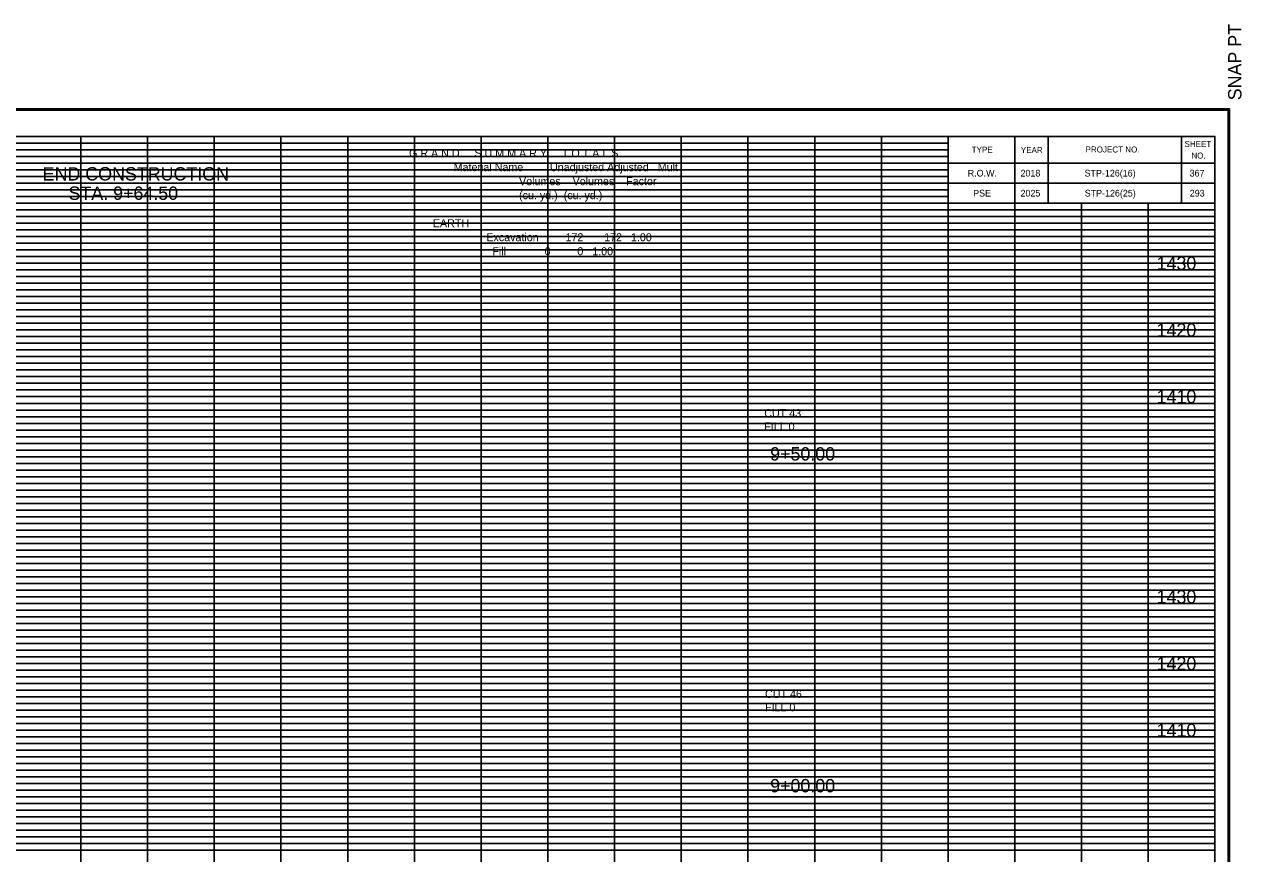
# Model space of a CAD drawing. Extents: x 980 to 1324, y 978 to 1227.
# Drawn here: x 1141.5 to 1324, y 1102.5 to 1226.8 of the extents above; entities that cross this region are included whole.
import ezdxf

# ---------------------------------------------------------------- set-up
doc = ezdxf.new("R2010")
doc.units = 0
for name, color, linetype in [('DESIGN - SCRATCH - User 1', 7, 'Continuous'), ('DESIGN - SHEET - Corner Text', 7, 'Continuous'), ('DESIGN - SHEET - Light Grid', 7, 'Continuous'), ('DESIGN - SHEET - Linework', 7, 'Continuous'), ('DESIGN - SHEET - Plot Shape', 7, 'Continuous'), ('DESIGN - TYPICAL - Text', 7, 'Continuous')]:
    doc.layers.add(name, color=color, linetype=linetype)

msp = doc.modelspace()

# ---------------------------------------------------------------- linework, layer by layer
at = {"layer": 'DESIGN - SCRATCH - User 1'}
for p, q in [((1285, 1204.5), (1285, 1204.5)), ((1292.4, 1204.5), (1292.4, 1204.5)), ((1304.9, 1204.5), (1304.9, 1204.5)), ((1317.4, 1204.5), (1317.4, 1204.5)), ((1285, 1201.5), (1285, 1201.5)), ((1292.4, 1201.5), (1292.4, 1201.5)), ((1304.9, 1201.5), (1304.9, 1201.5)), ((1317.4, 1201.5), (1317.4, 1201.5))]:
    msp.add_line(p, q, dxfattribs=at)
at = {"layer": 'DESIGN - SHEET - Light Grid'}
for p, q in [((1080, 1209), (1160, 1209)), ((1080, 1208), (1160, 1208)), ((1160, 1209), (1240, 1209)), ((1160, 1208), (1240, 1208)), ((1240, 1209), (1280, 1209)), ((1240, 1208), (1280, 1208)), ((1080, 1207), (1160, 1207)), ((1160, 1207), (1240, 1207)), ((1240, 1207), (1280, 1207)), ((1080, 1206), (1160, 1206)), ((1080, 1205), (1160, 1205)), ((1160, 1206), (1240, 1206)), ((1160, 1205), (1240, 1205)), ((1240, 1206), (1280, 1206)), ((1240, 1205), (1280, 1205)), ((1080, 1204), (1160, 1204)), ((1080, 1203), (1160, 1203)), ((1160, 1204), (1240, 1204)), ((1160, 1203), (1240, 1203)), ((1240, 1204), (1280, 1204)), ((1240, 1203), (1280, 1203)), ((1080, 1202), (1160, 1202)), ((1080, 1201), (1160, 1201)), ((1160, 1202), (1240, 1202)), ((1160, 1201), (1240, 1201)), ((1240, 1202), (1280, 1202)), ((1240, 1201), (1280, 1201)), ((1080, 1199), (1160, 1199)), ((1160, 1199), (1240, 1199)), ((1240, 1199), (1320, 1199)), ((1080, 1198), (1160, 1198)), ((1080, 1197), (1160, 1197)), ((1160, 1198), (1240, 1198)), ((1160, 1197), (1240, 1197)), ((1240, 1198), (1320, 1198)), ((1240, 1197), (1320, 1197)), ((1080, 1196), (1160, 1196)), ((1160, 1196), (1240, 1196)), ((1240, 1196), (1320, 1196)), ((1080, 1195), (1160, 1195)), ((1080, 1194), (1160, 1194)), ((1160, 1195), (1240, 1195)), ((1160, 1194), (1240, 1194)), ((1240, 1195), (1320, 1195)), ((1240, 1194), (1320, 1194)), ((1080, 1193), (1160, 1193)), ((1080, 1192), (1160, 1192)), ((1160, 1193), (1240, 1193)), ((1160, 1192), (1240, 1192)), ((1240, 1193), (1320, 1193)), ((1240, 1192), (1320, 1192)), ((1080, 1191), (1160, 1191)), ((1160, 1191), (1240, 1191)), ((1240, 1191), (1320, 1191)), ((1080, 1189), (1160, 1189)), ((1080, 1188), (1160, 1188)), ((1160, 1189), (1240, 1189)), ((1160, 1188), (1240, 1188)), ((1240, 1189), (1320, 1189)), ((1240, 1188), (1320, 1188)), ((1080, 1187), (1160, 1187)), ((1160, 1187), (1240, 1187)), ((1240, 1187), (1320, 1187)), ((1080, 1186), (1160, 1186)), ((1080, 1185), (1160, 1185)), ((1160, 1186), (1240, 1186)), ((1160, 1185), (1240, 1185)), ((1240, 1186), (1320, 1186)), ((1240, 1185), (1320, 1185)), ((1080, 1184), (1160, 1184)), ((1080, 1183), (1160, 1183)), ((1160, 1184), (1240, 1184)), ((1160, 1183), (1240, 1183)), ((1240, 1184), (1320, 1184)), ((1240, 1183), (1320, 1183)), ((1080, 1182), (1160, 1182)), ((1080, 1181), (1160, 1181)), ((1160, 1182), (1240, 1182)), ((1160, 1181), (1240, 1181)), ((1240, 1182), (1320, 1182)), ((1240, 1181), (1320, 1181)), ((1080, 1179), (1160, 1179)), ((1160, 1179), (1240, 1179)), ((1240, 1179), (1320, 1179)), ((1080, 1178), (1160, 1178)), ((1080, 1177), (1160, 1177)), ((1160, 1178), (1240, 1178)), ((1160, 1177), (1240, 1177)), ((1240, 1178), (1320, 1178)), ((1240, 1177), (1320, 1177)), ((1080, 1176), (1160, 1176)), ((1160, 1176), (1240, 1176)), ((1240, 1176), (1320, 1176)), ((1080, 1175), (1160, 1175)), ((1080, 1174), (1160, 1174)), ((1160, 1175), (1240, 1175)), ((1160, 1174), (1240, 1174)), ((1240, 1175), (1320, 1175)), ((1240, 1174), (1320, 1174)), ((1080, 1173), (1160, 1173)), ((1080, 1172), (1160, 1172)), ((1160, 1173), (1240, 1173)), ((1160, 1172), (1240, 1172)), ((1240, 1173), (1320, 1173)), ((1240, 1172), (1320, 1172)), ((1080, 1171), (1160, 1171)), ((1160, 1171), (1240, 1171)), ((1240, 1171), (1320, 1171)), ((1080, 1169), (1160, 1169)), ((1080, 1168), (1160, 1168)), ((1160, 1169), (1240, 1169)), ((1160, 1168), (1240, 1168)), ((1240, 1169), (1320, 1169)), ((1240, 1168), (1320, 1168)), ((1080, 1167), (1160, 1167)), ((1080, 1166), (1160, 1166)), ((1160, 1167), (1240, 1167)), ((1160, 1166), (1240, 1166)), ((1240, 1167), (1320, 1167)), ((1240, 1166), (1320, 1166)), ((1080, 1165), (1160, 1165)), ((1160, 1165), (1240, 1165)), ((1240, 1165), (1320, 1165)), ((1080, 1164), (1160, 1164)), ((1080, 1163), (1160, 1163)), ((1160, 1164), (1240, 1164)), ((1160, 1163), (1240, 1163)), ((1240, 1164), (1320, 1164)), ((1240, 1163), (1320, 1163)), ((1080, 1162), (1160, 1162)), ((1080, 1161), (1160, 1161)), ((1160, 1162), (1240, 1162)), ((1160, 1161), (1240, 1161)), ((1240, 1162), (1320, 1162)), ((1240, 1161), (1320, 1161)), ((1080, 1159), (1160, 1159)), ((1160, 1159), (1240, 1159)), ((1240, 1159), (1320, 1159)), ((1080, 1158), (1160, 1158)), ((1080, 1157), (1160, 1157)), ((1160, 1158), (1240, 1158)), ((1160, 1157), (1240, 1157)), ((1240, 1158), (1320, 1158)), ((1240, 1157), (1320, 1157)), ((1080, 1156), (1160, 1156)), ((1160, 1156), (1240, 1156)), ((1240, 1156), (1320, 1156)), ((1080, 1155), (1160, 1155)), ((1080, 1154), (1160, 1154)), ((1160, 1155), (1240, 1155)), ((1160, 1154), (1240, 1154)), ((1240, 1155), (1320, 1155)), ((1240, 1154), (1320, 1154)), ((1080, 1153), (1160, 1153)), ((1080, 1152), (1160, 1152)), ((1160, 1153), (1240, 1153)), ((1160, 1152), (1240, 1152)), ((1240, 1153), (1320, 1153)), ((1240, 1152), (1320, 1152)), ((1080, 1151), (1160, 1151)), ((1160, 1151), (1240, 1151)), ((1240, 1151), (1320, 1151)), ((1080, 1149), (1160, 1149)), ((1080, 1148), (1160, 1148)), ((1160, 1149), (1240, 1149)), ((1160, 1148), (1240, 1148)), ((1240, 1149), (1320, 1149)), ((1240, 1148), (1320, 1148)), ((1080, 1147), (1160, 1147)), ((1080, 1146), (1160, 1146)), ((1160, 1147), (1240, 1147)), ((1160, 1146), (1240, 1146)), ((1240, 1147), (1320, 1147)), ((1240, 1146), (1320, 1146)), ((1080, 1145), (1160, 1145)), ((1160, 1145), (1240, 1145)), ((1240, 1145), (1320, 1145)), ((1080, 1144), (1160, 1144)), ((1080, 1143), (1160, 1143)), ((1160, 1144), (1240, 1144)), ((1160, 1143), (1240, 1143)), ((1240, 1144), (1320, 1144)), ((1240, 1143), (1320, 1143)), ((1080, 1142), (1160, 1142)), ((1080, 1141), (1160, 1141)), ((1160, 1142), (1240, 1142)), ((1160, 1141), (1240, 1141)), ((1240, 1142), (1320, 1142)), ((1240, 1141), (1320, 1141)), ((1080, 1139), (1160, 1139)), ((1160, 1139), (1240, 1139)), ((1240, 1139), (1320, 1139)), ((1080, 1138), (1160, 1138)), ((1080, 1137), (1160, 1137)), ((1160, 1138), (1240, 1138)), ((1160, 1137), (1240, 1137)), ((1240, 1138), (1320, 1138)), ((1240, 1137), (1320, 1137)), ((1080, 1136), (1160, 1136)), ((1080, 1135), (1160, 1135)), ((1160, 1136), (1240, 1136)), ((1160, 1135), (1240, 1135)), ((1240, 1136), (1320, 1136)), ((1240, 1135), (1320, 1135)), ((1080, 1134), (1160, 1134)), ((1160, 1134), (1240, 1134)), ((1240, 1134), (1320, 1134)), ((1080, 1133), (1160, 1133)), ((1080, 1132), (1160, 1132)), ((1160, 1133), (1240, 1133)), ((1160, 1132), (1240, 1132)), ((1240, 1133), (1320, 1133)), ((1240, 1132), (1320, 1132)), ((1080, 1131), (1160, 1131)), ((1160, 1131), (1240, 1131)), ((1240, 1131), (1320, 1131)), ((1080, 1129), (1160, 1129)), ((1080, 1128), (1160, 1128)), ((1160, 1129), (1240, 1129)), ((1160, 1128), (1240, 1128)), ((1240, 1129), (1320, 1129)), ((1240, 1128), (1320, 1128)), ((1080, 1127), (1160, 1127)), ((1080, 1126), (1160, 1126)), ((1160, 1127), (1240, 1127)), ((1160, 1126), (1240, 1126)), ((1240, 1127), (1320, 1127)), ((1240, 1126), (1320, 1126)), ((1080, 1125), (1160, 1125)), ((1160, 1125), (1240, 1125)), ((1240, 1125), (1320, 1125)), ((1080, 1124), (1160, 1124)), ((1080, 1123), (1160, 1123)), ((1160, 1124), (1240, 1124)), ((1160, 1123), (1240, 1123)), ((1240, 1124), (1320, 1124)), ((1240, 1123), (1320, 1123)), ((1080, 1122), (1160, 1122)), ((1080, 1121), (1160, 1121)), ((1160, 1122), (1240, 1122)), ((1160, 1121), (1240, 1121)), ((1240, 1122), (1320, 1122)), ((1240, 1121), (1320, 1121)), ((1080, 1119), (1160, 1119)), ((1160, 1119), (1240, 1119)), ((1240, 1119), (1320, 1119)), ((1080, 1118), (1160, 1118)), ((1080, 1117), (1160, 1117)), ((1160, 1118), (1240, 1118)), ((1160, 1117), (1240, 1117)), ((1240, 1118), (1320, 1118)), ((1240, 1117), (1320, 1117)), ((1080, 1116), (1160, 1116)), ((1080, 1115), (1160, 1115)), ((1160, 1116), (1240, 1116)), ((1160, 1115), (1240, 1115)), ((1240, 1116), (1320, 1116)), ((1240, 1115), (1320, 1115)), ((1080, 1114), (1160, 1114)), ((1160, 1114), (1240, 1114)), ((1240, 1114), (1320, 1114)), ((1080, 1113), (1160, 1113)), ((1080, 1112), (1160, 1112)), ((1160, 1113), (1240, 1113)), ((1160, 1112), (1240, 1112)), ((1240, 1113), (1320, 1113)), ((1240, 1112), (1320, 1112)), ((1080, 1111), (1160, 1111)), ((1160, 1111), (1240, 1111)), ((1240, 1111), (1320, 1111)), ((1080, 1109), (1160, 1109)), ((1080, 1108), (1160, 1108)), ((1160, 1109), (1240, 1109)), ((1160, 1108), (1240, 1108)), ((1240, 1109), (1320, 1109)), ((1240, 1108), (1320, 1108)), ((1080, 1107), (1160, 1107)), ((1080, 1106), (1160, 1106)), ((1160, 1107), (1240, 1107)), ((1160, 1106), (1240, 1106)), ((1240, 1107), (1320, 1107)), ((1240, 1106), (1320, 1106)), ((1080, 1105), (1160, 1105)), ((1080, 1104), (1160, 1104)), ((1160, 1105), (1240, 1105)), ((1160, 1104), (1240, 1104)), ((1240, 1105), (1320, 1105)), ((1240, 1104), (1320, 1104)), ((1080, 1103), (1160, 1103)), ((1160, 1103), (1240, 1103)), ((1240, 1103), (1320, 1103))]:
    msp.add_line(p, q, dxfattribs=at)
at = {"layer": 'DESIGN - SHEET - Linework'}
for p, q in [((981.77, 1214.14), (1322.17, 1214.14)), ((1322.17, 1214.14), (1322.17, 995.86)), ((1150, 1000), (1150, 1210)), ((1160, 1000), (1160, 1210)), ((1170, 1000), (1170, 1210)), ((1180, 1000), (1180, 1210)), ((1190, 1000), (1190, 1210)), ((1200, 1000), (1200, 1210)), ((1210, 1000), (1210, 1210)), ((1220, 1000), (1220, 1210)), ((1230, 1000), (1230, 1210)), ((1240, 1000), (1240, 1210)), ((1250, 1000), (1250, 1210)), ((1260, 1000), (1260, 1210)), ((1270, 1000), (1270, 1210)), ((1000, 1200), (1280, 1200)), ((1280, 1000), (1280, 1200)), ((1290, 1000), (1290, 1200)), ((1300, 1000), (1300, 1200)), ((1310, 1000), (1310, 1200)), ((1000, 1190), (1320, 1190)), ((1000, 1180), (1320, 1180)), ((1000, 1170), (1320, 1170)), ((1000, 1160), (1320, 1160)), ((1000, 1150), (1320, 1150)), ((1000, 1140), (1320, 1140)), ((1000, 1130), (1320, 1130)), ((1000, 1120), (1320, 1120)), ((1000, 1110), (1320, 1110))]:
    msp.add_line(p, q, dxfattribs=at)
for points in [[(1000, 1210), (1000, 1000), (1320, 1000), (1320, 1210), (1000, 1210)], [(1280, 1210), (1280, 1200), (1320, 1200), (1320, 1210), (1315, 1210), (1315, 1200), (1295, 1200), (1295, 1210), (1290, 1210), (1290, 1200), (1320, 1200), (1280, 1200), (1280, 1203), (1320, 1203), (1320, 1206), (1280, 1206)]]:
    msp.add_lwpolyline(points, dxfattribs=at)
at = {"layer": 'DESIGN - SHEET - Plot Shape'}
for points in [[(981.97, 1213.94), (1321.97, 1213.94), (1321.97, 996.06), (981.97, 996.06)], [(991.5, 1210), (1320, 1210), (1320, 997.5), (991.5, 997.5)]]:
    msp.add_lwpolyline(points, close=True, dxfattribs=at)

# ---------------------------------------------------------------- texts
at = {"layer": 'DESIGN - SHEET - Corner Text'}
msp.add_text('  SNAP PT', height=2, rotation=90, dxfattribs=at).set_placement((1323.97, 1213.94))
for s, height, p in [('TYPE', 0.9, (1283.54, 1207.56)), ('YEAR', 0.9, (1290.9, 1207.52)), ('PROJECT NO.', 0.9, (1300.6, 1207.6)), ('SHEET', 0.9, (1315.43, 1208.43)), ('NO.', 0.9, (1316.46, 1206.69)), ('R.O.W.', 1, (1282.94, 1204)), ('2018', 1, (1290.85, 1204)), ('STP-126(16)', 1, (1300.45, 1204)), ('367', 1, (1316.2, 1204)), ('PSE', 1, (1283.75, 1201)), ('2025', 1, (1290.85, 1201)), ('STP-126(25)', 1, (1300.47, 1201)), ('293', 1, (1316.22, 1201)), ('1430', 2, (1311.25, 1190)), ('1420', 2, (1311.25, 1180)), ('1410', 2, (1311.25, 1170)), ('9+50.00', 2, (1253.32, 1161.43)), ('1430', 2, (1311.25, 1140)), ('1420', 2, (1311.25, 1130)), ('1410', 2, (1311.25, 1120)), ('9+00.00', 2, (1253.32, 1111.69))]:
    msp.add_text(s, height=height, dxfattribs=at).set_placement(p)
at = {"layer": 'DESIGN - TYPICAL - Text'}
for s, height, p in [('G R A N D     S U M M A R Y     T O T A L S', 1.2, (1199.19, 1206.9)), ('END CONSTRUCTION', 2, (1144.28, 1203.4)), ('               Material Name         Unadjusted Adjusted   Mult', 1.2, (1199.19, 1204.8)), ('STA. 9+64.50', 2, (1148.15, 1200.5)), ('                                     Volumes    Volumes    Factor', 1.2, (1199.19, 1202.7)), ('                                     (cu. yd.)  (cu. yd.)', 1.2, (1199.19, 1200.6)), ('        ---------------------------- ---------- ---------- ------', 1.2, (1199.19, 1198.5)), ('        EARTH', 1.2, (1199.19, 1196.4)), ('                          Excavation         172       172   1.00', 1.2, (1199.19, 1194.3)), ('                            Fill             0         0   1.00', 1.2, (1199.19, 1192.2)), ('CUT 43', 1.2, (1252.44, 1167.93)), ('FILL 0', 1.2, (1252.44, 1165.93)), ('CUT 46', 1.2, (1252.55, 1125.83)), ('FILL 0', 1.2, (1252.55, 1123.83))]:
    msp.add_text(s, height=height, dxfattribs=at).set_placement(p)

doc.saveas('drawing.dxf')
